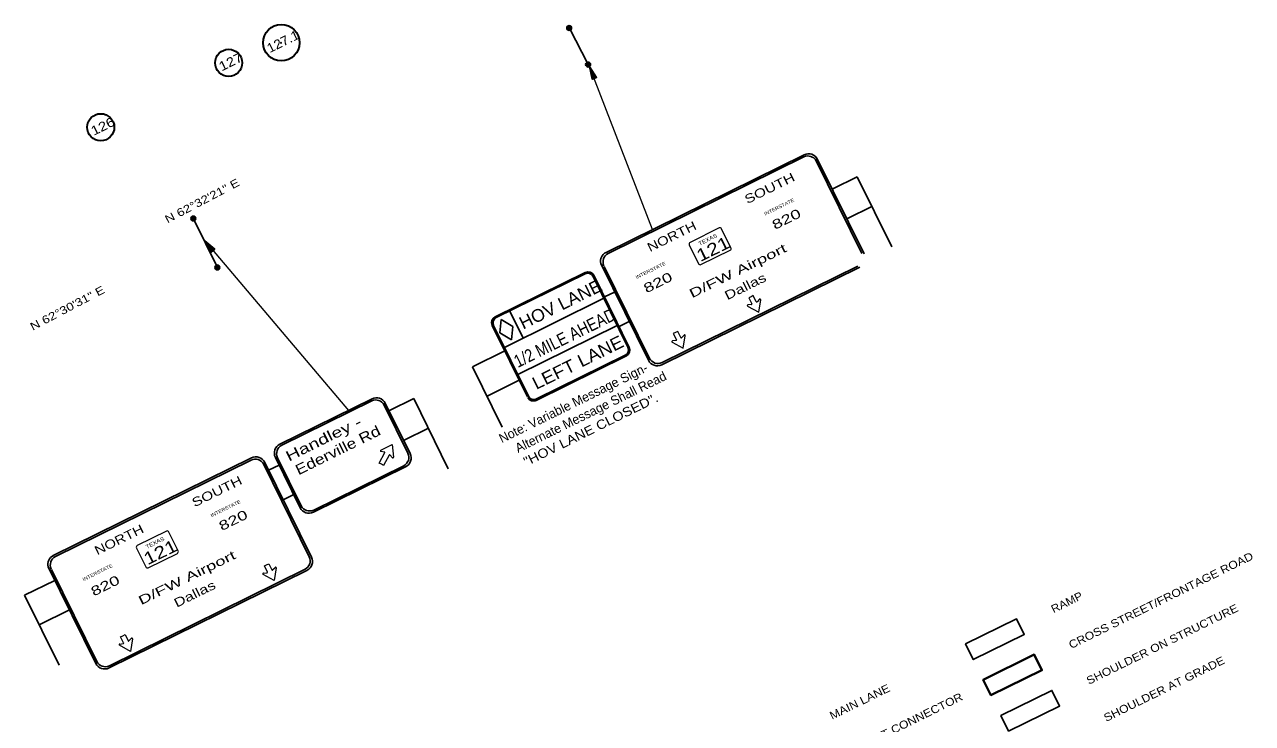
# Model space of a CAD drawing. Extents: x 2356431 to 2371438, y 6972864 to 6982525.
# Drawn here: x 2358405 to 2360268, y 6975326 to 6976387 of the extents above; entities that cross this region are included whole.
import ezdxf
from ezdxf.enums import TextEntityAlignment as Align

# ---------------------------------------------------------------- set-up
doc = ezdxf.new("R2010")
doc.units = 0
doc.header["$LTSCALE"] = 5.6
for name, color, linetype, lineweight in [('1', 7, 'Continuous', 25), ('17', 7, 'Continuous', 35), ('28', 7, 'Continuous', 35), ('48', 7, 'Continuous', 25), ('53', 7, 'Continuous', 13), ('61', 7, 'Continuous', 13), ('62', 7, 'Continuous', 25)]:
    doc.layers.add(name, color=color, linetype=linetype, lineweight=lineweight)

msp = doc.modelspace()

# ---------------------------------------------------------------- hatches: boundary and pattern name
at = {"layer": '48'}
for points in [[(2359235.436, 6976381.663, 1), (2359227.973, 6976381.567, 1)], [(2359264.126, 6976326.127, 1), (2359256.663, 6976326.031, 1)], [(2359262.494, 6976322.923), (2359266.708, 6976303.847), (2359273.334, 6976306.68)], [(2358665.201, 6976092.342, 1), (2358657.74, 6976092.545, 1)], [(2358679.099, 6976058.557), (2358688.537, 6976041.455), (2358694.086, 6976046.023)], [(2358701.604, 6976018.163, 1), (2358694.143, 6976018.366, 1)]]:
    msp.add_hatch(color=256, dxfattribs=at).paths.add_polyline_path(points)

# ---------------------------------------------------------------- linework, layer by layer
at = {"layer": '1', "lineweight": 40}
msp.add_lwpolyline([(2359871.645, 6975368.864), (2359948.864, 6975406.974), (2359937.215, 6975430.577), (2359859.996, 6975392.467)], close=True, dxfattribs=at)
at = {"layer": '1'}
msp.add_circle((2358794.449, 6976358.96), 0.53, dxfattribs=at)
at = {"layer": '17'}
for centre, radius in [((2358794.924, 6976359.194), 27.632), ((2358715.055, 6976328.712), 20.576), ((2358520.986, 6976230.965), 20.576)]:
    msp.add_circle(centre, radius, dxfattribs=at)
at = {"layer": '48'}
for p, q in [((2359232.247, 6976381.197), (2359260.261, 6976326.269)), ((2359588.208, 6976189.3), (2359287.609, 6976041.011)), ((2359587.78, 6976185.959), (2359290.877, 6976039.481)), ((2359675.874, 6976039.122), (2359606.273, 6976180.208)), ((2359679.236, 6976038.684), (2359608.441, 6976182.188)), ((2359631.82, 6976137.48), (2359668.678, 6976155.671)), ((2359668.678, 6976155.671), (2359721.119, 6976049.416)), ((2359653.95, 6976092.642), (2359690.808, 6976110.832)), ((2358661.728, 6976092.005), (2358697.662, 6976019.195)), ((2359279.661, 6976024.051), (2359352.072, 6975877.285)), ((2359284.842, 6976019.897), (2359353.754, 6975880.207)), ((2359372.157, 6975870.473), (2359672.417, 6976018.594)), ((2359372.593, 6975873.813), (2359669.497, 6976020.292)), ((2359119.248, 6975943.089), (2359256.145, 6976010.648)), ((2359121.109, 6975942.018), (2359255.855, 6976008.525)), ((2359320.814, 6975897.173), (2359267.871, 6976004.448)), ((2359268.946, 6976006.306), (2359304.134, 6975935.013)), ((2359322.949, 6975896.889), (2359268.946, 6976006.306)), ((2359285.187, 6975973.401), (2359300.336, 6975980.878)), ((2359133.361, 6975896.93), (2359284.192, 6975971.376)), ((2359141.423, 6975952.045), (2359161.717, 6975910.926)), ((2359114.905, 6975930.281), (2359168.379, 6975821.93)), ((2359117.043, 6975930.003), (2359169.978, 6975822.721)), ((2359126.282, 6975918.899), (2359128.607, 6975939.403)), ((2359128.607, 6975939.403), (2359146.293, 6975928.775)), ((2359143.969, 6975908.274), (2359146.293, 6975928.775)), ((2359153.651, 6975855.81), (2359304.487, 6975930.257)), ((2359307.317, 6975928.564), (2359322.458, 6975936.037)), ((2359126.282, 6975918.899), (2359143.969, 6975908.274)), ((2359084.919, 6975867.565), (2359133.922, 6975891.751)), ((2359084.919, 6975867.565), (2359130.256, 6975775.705)), ((2359318.604, 6975884.084), (2359181.712, 6975816.513)), ((2359316.734, 6975885.16), (2359181.991, 6975818.653)), ((2359107.05, 6975822.728), (2359156.05, 6975846.913)), ((2358932.557, 6975819.013), (2358792.707, 6975750.019)), ((2358932.114, 6975815.658), (2358795.636, 6975748.33)), ((2358952.634, 6975812.195), (2358990.328, 6975735.766)), ((2358959.023, 6975800.888), (2358995.881, 6975819.079)), ((2358995.881, 6975819.079), (2359048.322, 6975712.824)), ((2358986.98, 6975736.201), (2358950.943, 6975809.266)), ((2358981.153, 6975756.05), (2359018.011, 6975774.24)), ((2358749.67, 6975729.204), (2358449.071, 6975580.915)), ((2358749.242, 6975725.863), (2358452.339, 6975579.385)), ((2358837.336, 6975579.026), (2358767.735, 6975720.112)), ((2358840.698, 6975578.588), (2358769.903, 6975722.092)), ((2358823.573, 6975653.499), (2358785.888, 6975729.928)), ((2358789.242, 6975729.493), (2358825.281, 6975656.429)), ((2358775.672, 6975710.398), (2358791.635, 6975718.276)), ((2358843.655, 6975646.685), (2358983.497, 6975715.67)), ((2358844.107, 6975650.039), (2358980.586, 6975717.374)), ((2358797.794, 6975665.556), (2358813.755, 6975673.433)), ((2358441.123, 6975563.955), (2358513.534, 6975417.189)), ((2358446.304, 6975559.801), (2358515.216, 6975420.111)), ((2358533.619, 6975410.377), (2358833.879, 6975558.498)), ((2358534.055, 6975413.717), (2358830.959, 6975560.196)), ((2358405.417, 6975520.711), (2358451.289, 6975543.351)), ((2358405.417, 6975520.711), (2358457.858, 6975414.456)), ((2358427.547, 6975475.871), (2358473.414, 6975498.508))]:
    msp.add_line(p, q, dxfattribs=at)
at = {"layer": '48', "lineweight": 13}
for p, q in [((2359358.188, 6976075.829), (2359262.494, 6976322.923)), ((2359459.201, 6976078.074), (2359415.047, 6976056.295)), ((2359477.093, 6976048.163), (2359462.967, 6976076.803)), ((2358679.099, 6976058.557), (2358896.767, 6975801.268)), ((2359413.767, 6976052.529), (2359427.898, 6976023.897)), ((2359431.665, 6976022.616), (2359475.812, 6976044.398)), ((2358620.663, 6975617.978), (2358576.509, 6975596.199)), ((2358638.555, 6975588.067), (2358624.429, 6975616.707)), ((2358575.229, 6975592.433), (2358589.36, 6975563.801)), ((2358593.127, 6975562.52), (2358637.274, 6975584.302))]:
    msp.add_line(p, q, dxfattribs=at)
at = {"layer": '48'}
for points in [[(2359262.494, 6976322.923), (2359266.708, 6976303.847), (2359273.334, 6976306.68)], [(2358679.099, 6976058.557), (2358688.537, 6976041.455), (2358694.086, 6976046.023)]]:
    msp.add_lwpolyline(points, close=True, dxfattribs=at)
for centre in [(2359231.704, 6976381.615), (2359260.394, 6976326.079), (2358661.471, 6976092.443), (2358697.873, 6976018.265)]:
    msp.add_circle(centre, 3.732, dxfattribs=at)
for centre, radius, start, end in [((2359594.002, 6976173.342), 14.063, 29.21774, 116.25867), ((2359594.847, 6976175.85), 15.001, 24.97747, 116.25867), ((2359294.252, 6976027.554), 15.001, 116.25867, 193.48473), ((2359297.099, 6976026.868), 14.063, 116.25867, 206.25867), ((2359259.832, 6976000.473), 8.966, 26.26515, 116.26515), ((2359260.375, 6976002.074), 9.563, 26.26515, 116.26515), ((2359123.479, 6975934.515), 9.563, 116.26456, 206.26456), ((2359125.08, 6975933.972), 8.966, 116.26456, 206.26456), ((2359312.766, 6975893.199), 8.966, 296.26515, 26.26515), ((2359314.367, 6975892.656), 9.563, 296.26515, 26.26515), ((2359365.522, 6975883.916), 15.001, 206.25867, 296.25867), ((2359366.374, 6975886.428), 14.063, 206.25867, 296.25867), ((2358938.345, 6975803.048), 14.057, 26.25867, 116.25867), ((2358939.196, 6975805.558), 14.995, 26.25867, 116.25867), ((2359177.479, 6975825.09), 9.563, 206.26456, 296.26456), ((2359178.022, 6975826.691), 8.966, 206.26456, 296.26456), ((2358799.344, 6975736.564), 14.995, 116.25867, 206.25867), ((2358801.854, 6975735.713), 14.057, 116.25867, 206.25867), ((2358755.463, 6975713.246), 14.063, 29.21774, 116.25867), ((2358756.308, 6975715.754), 15.001, 24.97747, 116.25867), ((2358974.373, 6975729.982), 14.057, 296.25867, 26.25867), ((2358976.88, 6975729.132), 14.995, 296.25867, 26.25867), ((2358837.02, 6975660.133), 14.995, 206.25867, 296.25867), ((2358837.887, 6975662.648), 14.057, 206.25867, 296.25867), ((2358455.712, 6975567.458), 15.001, 116.25867, 193.48473), ((2358458.56, 6975566.772), 14.063, 116.25867, 206.25867), ((2358824.73, 6975572.803), 14.063, 296.25867, 26.25867), ((2358827.241, 6975571.951), 15.001, 296.25867, 26.25867), ((2358526.982, 6975423.82), 15.001, 206.25867, 296.25867), ((2358527.834, 6975426.332), 14.063, 206.25867, 296.25867)]:
    msp.add_arc(centre, radius, start, end, dxfattribs=at)
at = {"layer": '48', "lineweight": 13}
for centre, start, end in [((2359460.446, 6976075.561), 26.25867, 116.25867), ((2359416.288, 6976053.776), 116.25867, 206.25867), ((2359474.574, 6976046.923), 296.25867, 26.25867), ((2359430.415, 6976025.139), 206.25867, 296.25867), ((2358621.906, 6975615.465), 26.25867, 116.25867), ((2358577.748, 6975593.68), 116.25867, 206.25867), ((2358636.034, 6975586.827), 296.25867, 26.25867), ((2358591.876, 6975565.043), 206.25867, 296.25867)]:
    msp.add_arc(centre, 2.813, start, end, dxfattribs=at)
at = {"layer": '53'}
for p, q in [((2359508.306, 6975961.902), (2359502.794, 6975961.297)), ((2359520.543, 6975970.046), (2359516.717, 6975966.053)), ((2359519.299, 6975950.198), (2359522.265, 6975969.141)), ((2359502.473, 6975959.379), (2359519.299, 6975950.198)), ((2359387.93, 6975904.906), (2359404.755, 6975895.723)), ((2359393.772, 6975907.435), (2359388.26, 6975906.822)), ((2359406, 6975915.578), (2359402.173, 6975911.578)), ((2359404.755, 6975895.723), (2359407.722, 6975914.666)), ((2358943.384, 6975721.439), (2358952.038, 6975737.124)), ((2358951.493, 6975738.106), (2358946.057, 6975738.961)), ((2358963.403, 6975729.428), (2358959.754, 6975733.609)), ((2358767.803, 6975554.311), (2358773.315, 6975554.916)), ((2358776.02, 6975568.546), (2358780.618, 6975559.231)), ((2358781.726, 6975559.067), (2358785.552, 6975563.06)), ((2358549.722, 6975446.726), (2358555.234, 6975447.339))]:
    msp.add_line(p, q, dxfattribs=at)
for points in [[(2359515.609, 6975966.217), (2359511.011, 6975975.532), (2359507.625, 6975973.859), (2359504.238, 6975972.195), (2359508.835, 6975962.871)], [(2359401.065, 6975911.741), (2359396.475, 6975921.064), (2359393.08, 6975919.384), (2359389.702, 6975917.72), (2359394.293, 6975908.404)], [(2358945.793, 6975740.878), (2358962.968, 6975749.347), (2358965.138, 6975730.286)], [(2358958.597, 6975733.502), (2358950.109, 6975717.772), (2358946.71, 6975719.624), (2358943.384, 6975721.439)], [(2358787.274, 6975562.155), (2358784.308, 6975543.212), (2358767.482, 6975552.393)], [(2358773.844, 6975555.885), (2358769.247, 6975565.209), (2358772.634, 6975566.873), (2358776.02, 6975568.546)], [(2358555.755, 6975448.308), (2358551.164, 6975457.624), (2358554.542, 6975459.288), (2358557.937, 6975460.968), (2358562.527, 6975451.645)], [(2358569.184, 6975454.57), (2358566.217, 6975435.627), (2358549.392, 6975444.81)], [(2358563.635, 6975451.482), (2358567.462, 6975455.482), (2358567.457, 6975455.463)]]:
    msp.add_lwpolyline(points, dxfattribs=at)
for centre, radius, start, end in [((2359502.93, 6975960.287), 1.012, 96.13904, 241.52017), ((2359508.24, 6975962.562), 0.675, 276.27556, 26.25867), ((2359516.231, 6975966.504), 0.675, 206.25867, 316.24177), ((2359521.268, 6975969.334), 1.012, 350.99716, 136.3783), ((2359388.391, 6975905.814), 1.012, 96.13904, 241.52017), ((2359393.702, 6975908.089), 0.675, 276.27556, 26.25867), ((2359401.692, 6975912.031), 0.675, 206.25867, 316.24177), ((2359406.729, 6975914.861), 1.012, 350.99716, 136.3783), ((2358946.229, 6975739.958), 1.012, 115.99716, 261.3783), ((2358951.434, 6975737.456), 0.675, 331.25867, 81.24177), ((2358959.243, 6975733.173), 0.675, 41.27556, 151.25867), ((2358964.151, 6975730.129), 1.012, 221.13904, 6.52017), ((2358767.938, 6975553.3), 1.012, 96.13904, 241.52017), ((2358773.249, 6975555.575), 0.675, 276.27556, 26.25867), ((2358781.24, 6975559.517), 0.675, 206.25867, 316.24177), ((2358786.277, 6975562.347), 1.012, 350.99716, 136.3783), ((2358549.851, 6975445.718), 1.012, 96.13904, 241.52017), ((2358555.162, 6975447.993), 0.675, 276.27556, 26.25867), ((2358563.153, 6975451.935), 0.675, 206.25867, 316.24177), ((2358568.19, 6975454.765), 1.012, 350.99716, 136.3783)]:
    msp.add_arc(centre, radius, start, end, dxfattribs=at)
at = {"layer": '62'}
for points in [[(2359833.189, 6975446.785), (2359910.407, 6975484.895), (2359922.056, 6975461.292), (2359844.837, 6975423.182)], [(2359844.837, 6975423.182), (2359922.056, 6975461.292), (2359910.407, 6975484.895), (2359833.189, 6975446.785)], [(2359859.996, 6975392.467), (2359937.215, 6975430.577), (2359948.864, 6975406.974), (2359871.645, 6975368.864)], [(2359886.804, 6975338.149), (2359964.023, 6975376.259), (2359975.672, 6975352.656), (2359898.453, 6975314.546)], [(2359898.453, 6975314.546), (2359975.672, 6975352.656), (2359964.023, 6975376.259), (2359886.804, 6975338.149)]]:
    msp.add_lwpolyline(points, close=True, dxfattribs=at)

# ---------------------------------------------------------------- texts
at = {"layer": '17'}
for s, width, p in [('127.1', 1.1, (2358800.552, 6976354.824)), ('127', 1.2, (2358721.251, 6976323.963)), ('126', 1.2, (2358527.181, 6976226.216))]:
    msp.add_text(s, height=14, rotation=26.268, dxfattribs=dict(at, width=width)).set_placement(p, align=Align.CENTER)
at = {"layer": '28', "width": 1.25}
for s, p in [('N 62°32\'21" E', (2358677.565, 6976114.045)), ('N 62°30\'31" E', (2358473.057, 6975951.199))]:
    msp.add_text(s, height=12, rotation=27.784, dxfattribs=at).set_placement(p, align=Align.CENTER)
at = {"layer": '48'}
for s, height, rotation, width, p in [('SOUTH', 13.5, 26.259, 1.3, (2359538.746, 6976132.378)), ('NORTH', 13.5, 26.259, 1.25, (2359390.324, 6976059.165)), ('D/FW Airport', 13.5, 26.259, 1.55, (2359490.462, 6976007.103)), ('HOV LANE', 19.13, 26.264, 1.05, (2359222.755, 6975953.733)), ('Dallas', 13.5, 26.259, 1.35, (2359501.902, 6975983.311)), ('1/2 MILE AHEAD', 19.13, 26.264, 0.85, (2359229.138, 6975902.792)), ('LEFT LANE', 19.13, 26.264, 1.1, (2359248.946, 6975865.514)), ('Handley -', 15.62, 26.259, 1.4, (2358862.513, 6975751.126)), ('Ederville Rd', 15.62, 26.259, 1.25, (2358884.136, 6975733.822)), ('SOUTH', 13.5, 26.259, 1.3, (2358700.209, 6975672.28)), ('NORTH', 13.5, 26.259, 1.25, (2358551.786, 6975599.067)), ('D/FW Airport', 13.5, 26.259, 1.55, (2358654.709, 6975541.363)), ('Dallas', 13.5, 26.259, 1.35, (2358666.547, 6975516.765))]:
    msp.add_text(s, height=height, rotation=rotation, dxfattribs=dict(at, width=width)).set_placement(p, align=Align.CENTER)
for s, height, rotation, width, p in [('INTERSTATE', 5.197, 26.258, 1.15, (2359529.051, 6976096.652)), ('820', 14.18, 26.258, 1.45, (2359543.839, 6976075.107)), ('121', 18.75, 26.259, 1.25, (2359430.638, 6976026.245)), ('TEXAS', 6, 26.259, 1.15, (2359429.675, 6976051.138)), ('INTERSTATE', 5.197, 26.258, 1.15, (2359334.098, 6976000.436)), ('820', 14.18, 26.258, 1.45, (2359348.886, 6975978.891)), ('INTERSTATE', 5.197, 26.258, 1.15, (2358689.3, 6975639.011)), ('820', 14.18, 26.258, 1.45, (2358704.55, 6975618.075)), ('TEXAS', 6, 26.259, 1.15, (2358591.137, 6975591.04)), ('121', 18.75, 26.259, 1.25, (2358592.1, 6975566.147)), ('INTERSTATE', 5.197, 26.258, 1.15, (2358494.977, 6975541.944)), ('820', 14.18, 26.258, 1.45, (2358510.348, 6975518.793))]:
    msp.add_text(s, height=height, rotation=rotation, dxfattribs=dict(at, width=width)).set_placement(p)
at = {"layer": '61'}
for s, p in [('Note: Variable Message Sign-', (2359129.456, 6975751.275)), ('   Alternate Message Shall Read', (2359140.077, 6975729.751))]:
    msp.add_text(s, height=14, rotation=26.268, dxfattribs=at).set_placement(p)
at = {"layer": '61', "width": 1.15}
msp.add_text('   "HOV LANE CLOSED".', height=14, rotation=26.268, dxfattribs=at).set_placement((2359150.699, 6975708.23))
at = {"layer": '62'}
for s, width, p in [('CROSS STREET/FRONTAGE ROAD', 1.15, (2359993.315, 6975439.034)), ('RAMP', 1.1, (2359966.507, 6975493.352)), ('SHOULDER ON STRUCTURE', 1.15, (2360020.123, 6975384.716)), ('SHOULDER AT GRADE', 1.15, (2360046.423, 6975328.374)), ('MAIN LANE', 1.15, (2359630.529, 6975331.639)), ('DIRECT CONNECTOR', 1.15, (2359657.337, 6975277.321))]:
    msp.add_text(s, height=12, rotation=26.268, dxfattribs=dict(at, width=width)).set_placement(p)

doc.saveas('drawing.dxf')
